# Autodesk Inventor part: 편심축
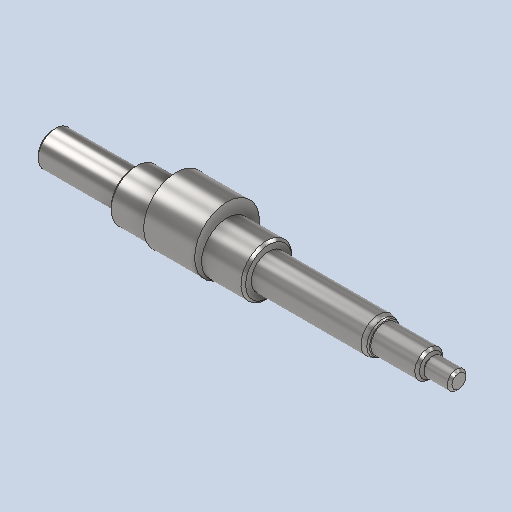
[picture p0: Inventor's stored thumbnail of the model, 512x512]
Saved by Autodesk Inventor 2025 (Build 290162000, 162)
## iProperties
Created: 2024-07
Part Number: 편심축
Material: 강철, 연강
Document SubType Name: Modeling
Designer: onair
Density: 7.86 g/cm^3
Appearance: 기본값
Author: jhkim
Sending System: Autodesk Inventor 2025
Preprocessor: ST-DEVELOPER v20
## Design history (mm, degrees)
feature "솔리드1"
node "솔리드2"
